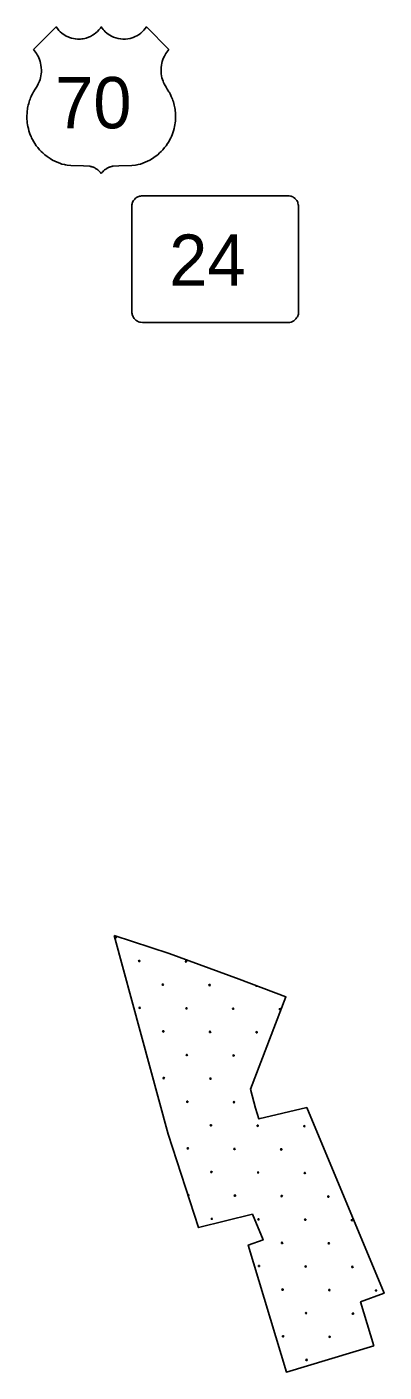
# Model space of a CAD drawing. Extents: x 1612280 to 1883141, y 560852 to 780851.
# Drawn here: x 1797202 to 1800143, y 676727 to 687794 of the extents above; entities that cross this region are included whole.
import ezdxf

# ---------------------------------------------------------------- set-up
doc = ezdxf.new("R2010")
doc.units = 0
for name, color, linetype in [('DESIGN - EROSION CONTROL - Devices', 7, 'Continuous'), ('DESIGN - ROW - Slope Lines', 7, 'Continuous'), ('DESIGN - SCRATCH - User 1', 7, 'Continuous'), ('SURVEY - DRAINAGE - Bridge Deck with Text', 7, 'Continuous')]:
    doc.layers.add(name, color=color, linetype=linetype)

msp = doc.modelspace()

# ---------------------------------------------------------------- linework, layer by layer
at = {"layer": 'DESIGN - EROSION CONTROL - Devices'}
for centre in [(1797933, 680303), (1797933, 680303), (1798127, 680109), (1798127, 680109), (1798512, 680105), (1798512, 680105), (1798321, 679915), (1798321, 679915), (1798706, 679911), (1798706, 679911), (1798131, 679724), (1798131, 679724), (1798516, 679720), (1798516, 679720), (1798900, 679717), (1798900, 679717), (1799285, 679713), (1799285, 679713), (1798325, 679530), (1798325, 679530), (1798710, 679526), (1798710, 679526), (1799094, 679523), (1799094, 679523), (1798519, 679336), (1798519, 679336), (1798904, 679332), (1798904, 679332), (1798329, 679146), (1798329, 679146), (1798714, 679142), (1798714, 679142), (1798523, 678951), (1798523, 678951), (1798908, 678948), (1798908, 678948), (1798717, 678757), (1798717, 678757), (1799102, 678754), (1799102, 678754), (1799486, 678750), (1799486, 678750), (1798527, 678567), (1798527, 678567), (1798911, 678563), (1798911, 678563), (1799296, 678559), (1799296, 678559), (1798721, 678373), (1798721, 678373), (1799106, 678369), (1799106, 678369), (1799490, 678365), (1799490, 678365), (1798915, 678179), (1798915, 678179), (1799300, 678175), (1799300, 678175), (1799684, 678171), (1799684, 678171), (1798725, 677988), (1798725, 677988), (1799109, 677984), (1799109, 677984), (1799494, 677981), (1799494, 677981), (1799878, 677977), (1799878, 677977), (1799303, 677790), (1799303, 677790), (1799688, 677787), (1799688, 677787), (1799113, 677600), (1799113, 677600), (1799498, 677596), (1799498, 677596), (1799882, 677592), (1799882, 677592), (1799307, 677406), (1799307, 677406), (1799692, 677402), (1799692, 677402), (1800076, 677398), (1800076, 677398), (1799501, 677212), (1799501, 677212), (1799886, 677208), (1799886, 677208), (1799311, 677021), (1799311, 677021), (1799695, 677017), (1799695, 677017), (1799505, 676827), (1799505, 676827)]:
    msp.add_circle(centre, 5.28, dxfattribs=at)
for centre, start, end in [((1799091, 679907), 157.0894, 340.6284), ((1798531, 678182), 263.9046, 131.9576)]:
    msp.add_arc(centre, 5.28, start, end, dxfattribs=at)
at = {"layer": 'DESIGN - ROW - Slope Lines'}
msp.add_line((1798066, 686304), (1798066, 685472), dxfattribs=at)
msp.add_line((1798066, 686304), (1798066, 685472), dxfattribs=at)
for points in [[(1799439, 686293), (1799439, 686301), (1799438, 686309), (1799437, 686324), (1799436, 686334), (1799434, 686345), (1799432, 686351), (1799429, 686358), (1799425, 686365), (1799419, 686372), (1799414, 686378), (1799409, 686383), (1799404, 686387), (1799397, 686392), (1799392, 686395), (1799384, 686399), (1799378, 686401), (1799371, 686402), (1799362, 686404), (1799353, 686404), (1799345, 686405), (1799332, 686405), (1799323, 686404), (1798166, 686405), (1798156, 686405), (1798146, 686404), (1798137, 686403), (1798128, 686402), (1798124, 686400), (1798116, 686397), (1798110, 686394), (1798105, 686391), (1798096, 686384), (1798090, 686378), (1798085, 686372), (1798081, 686367), (1798075, 686357), (1798071, 686350), (1798070, 686345), (1798069, 686341), (1798068, 686338), (1798067, 686330), (1798066, 686321), (1798066, 686313), (1798066, 686306), (1798066, 686288)], [(1799439, 686293), (1799439, 686301), (1799438, 686309), (1799437, 686324), (1799436, 686334), (1799434, 686345), (1799432, 686351), (1799429, 686358), (1799425, 686365), (1799419, 686372), (1799414, 686378), (1799409, 686383), (1799404, 686387), (1799397, 686392), (1799392, 686395), (1799384, 686399), (1799378, 686401), (1799371, 686402), (1799362, 686404), (1799353, 686404), (1799345, 686405), (1799332, 686405), (1799323, 686404), (1798166, 686405), (1798156, 686405), (1798146, 686404), (1798137, 686403), (1798128, 686402), (1798124, 686400), (1798116, 686397), (1798110, 686394), (1798105, 686391), (1798096, 686384), (1798090, 686378), (1798085, 686372), (1798081, 686367), (1798075, 686357), (1798071, 686350), (1798070, 686345), (1798069, 686341), (1798068, 686338), (1798067, 686330), (1798066, 686321), (1798066, 686313), (1798066, 686306), (1798066, 686288)], [(1799329, 685363), (1799349, 685363), (1799366, 685363), (1799377, 685366), (1799389, 685370), (1799400, 685377), (1799409, 685384), (1799417, 685392), (1799423, 685400), (1799429, 685409), (1799433, 685417), (1799436, 685424), (1799437, 685432), (1799438, 685440), (1799438, 685450), (1799439, 685473), (1799439, 686293)], [(1799329, 685363), (1799349, 685363), (1799366, 685363), (1799377, 685366), (1799389, 685370), (1799400, 685377), (1799409, 685384), (1799417, 685392), (1799423, 685400), (1799429, 685409), (1799433, 685417), (1799436, 685424), (1799437, 685432), (1799438, 685440), (1799438, 685450), (1799439, 685473), (1799439, 686293)], [(1798066, 685472), (1798066, 685463), (1798066, 685453), (1798067, 685443), (1798068, 685434), (1798070, 685425), (1798073, 685417), (1798076, 685410), (1798080, 685403), (1798086, 685395), (1798091, 685389), (1798099, 685382), (1798106, 685377), (1798114, 685372), (1798122, 685368), (1798131, 685365), (1798138, 685364), (1798153, 685363), (1798172, 685363), (1799329, 685363)], [(1798066, 685472), (1798066, 685463), (1798066, 685453), (1798067, 685443), (1798068, 685434), (1798070, 685425), (1798073, 685417), (1798076, 685410), (1798080, 685403), (1798086, 685395), (1798091, 685389), (1798099, 685382), (1798106, 685377), (1798114, 685372), (1798122, 685368), (1798131, 685365), (1798138, 685364), (1798153, 685363), (1798172, 685363), (1799329, 685363)]]:
    msp.add_lwpolyline(points, dxfattribs=at)
at = {"layer": 'DESIGN - SCRATCH - User 1'}
for points in [[(1797920, 680320), (1798374, 680171), (1798951, 679961), (1799335, 679813), (1799042, 679055)], [(1799060, 678025), (1798615, 677916), (1798366, 678685), (1797920, 680320)], [(1797920, 680320), (1798374, 680171), (1798951, 679961), (1799335, 679813), (1799042, 679055)], [(1799060, 678025), (1798615, 677916), (1798366, 678685), (1797920, 680320)], [(1799042, 679055), (1799085, 678899), (1799113, 678810), (1799506, 678904)], [(1799042, 679055), (1799085, 678899), (1799113, 678810), (1799506, 678904)], [(1799506, 678904), (1800143, 677375), (1799949, 677305), (1800058, 676943)], [(1799506, 678904), (1800143, 677375), (1799949, 677305), (1800058, 676943)], [(1800058, 676943), (1799339, 676727), (1799025, 677772), (1799147, 677815), (1799060, 678025)], [(1800058, 676943), (1799339, 676727), (1799025, 677772), (1799147, 677815), (1799060, 678025)]]:
    msp.add_lwpolyline(points, dxfattribs=at)
at = {"layer": 'SURVEY - DRAINAGE - Bridge Deck with Text'}
for points in [[(1797256, 687608), (1797443, 687794), (1797453, 687781), (1797465, 687766), (1797477, 687754), (1797489, 687744), (1797501, 687734), (1797514, 687726), (1797526, 687719), (1797541, 687712), (1797554, 687707), (1797570, 687702), (1797586, 687698), (1797602, 687695), (1797620, 687694), (1797628, 687694), (1797636, 687694), (1797644, 687694), (1797654, 687695), (1797665, 687697), (1797678, 687699), (1797691, 687702), (1797709, 687709), (1797726, 687716), (1797742, 687725), (1797756, 687734), (1797770, 687745), (1797783, 687756), (1797795, 687769), (1797807, 687783), (1797814, 687794), (1797821, 687784), (1797830, 687773), (1797838, 687764), (1797847, 687755), (1797859, 687744), (1797871, 687735), (1797885, 687726), (1797898, 687719), (1797914, 687711), (1797933, 687704), (1797954, 687699), (1797975, 687695), (1797993, 687694), (1798013, 687694), (1798033, 687696), (1798053, 687700), (1798076, 687707), (1798093, 687714), (1798108, 687722), (1798125, 687732), (1798139, 687743), (1798155, 687757), (1798166, 687768), (1798176, 687780), (1798186, 687794), (1798372, 687608)], [(1797256, 687608), (1797443, 687794), (1797453, 687781), (1797465, 687766), (1797477, 687754), (1797489, 687744), (1797501, 687734), (1797514, 687726), (1797526, 687719), (1797541, 687712), (1797554, 687707), (1797570, 687702), (1797586, 687698), (1797602, 687695), (1797620, 687694), (1797628, 687694), (1797636, 687694), (1797644, 687694), (1797654, 687695), (1797665, 687697), (1797678, 687699), (1797691, 687702), (1797709, 687709), (1797726, 687716), (1797742, 687725), (1797756, 687734), (1797770, 687745), (1797783, 687756), (1797795, 687769), (1797807, 687783), (1797814, 687794), (1797821, 687784), (1797830, 687773), (1797838, 687764), (1797847, 687755), (1797859, 687744), (1797871, 687735), (1797885, 687726), (1797898, 687719), (1797914, 687711), (1797933, 687704), (1797954, 687699), (1797975, 687695), (1797993, 687694), (1798013, 687694), (1798033, 687696), (1798053, 687700), (1798076, 687707), (1798093, 687714), (1798108, 687722), (1798125, 687732), (1798139, 687743), (1798155, 687757), (1798166, 687768), (1798176, 687780), (1798186, 687794), (1798372, 687608)], [(1797256, 687608), (1797265, 687597), (1797273, 687586), (1797281, 687575), (1797287, 687565), (1797294, 687553), (1797300, 687539), (1797306, 687525), (1797311, 687509), (1797315, 687495), (1797318, 687479), (1797320, 687461), (1797322, 687439), (1797321, 687423), (1797320, 687407), (1797318, 687393), (1797314, 687375), (1797310, 687361), (1797305, 687348), (1797300, 687336), (1797296, 687325), (1797288, 687312), (1797281, 687299), (1797270, 687281), (1797257, 687260), (1797254, 687254), (1797248, 687243), (1797241, 687230), (1797237, 687221), (1797232, 687210), (1797228, 687199), (1797224, 687188), (1797220, 687177), (1797217, 687164), (1797213, 687151), (1797211, 687140), (1797208, 687127), (1797206, 687116), (1797205, 687103), (1797203, 687091), (1797203, 687080), (1797202, 687069), (1797202, 687058), (1797202, 687045), (1797202, 687034), (1797204, 687019), (1797205, 687004), (1797207, 686989), (1797210, 686974), (1797214, 686958), (1797219, 686939), (1797224, 686924), (1797230, 686906), (1797236, 686893), (1797241, 686881), (1797249, 686867), (1797258, 686849), (1797267, 686834), (1797279, 686817), (1797292, 686801), (1797306, 686784), (1797320, 686769), (1797333, 686757), (1797350, 686742), (1797369, 686727), (1797394, 686711), (1797414, 686699), (1797433, 686689), (1797451, 686681), (1797472, 686673), (1797491, 686666), (1797511, 686661), (1797521, 686659), (1797533, 686657), (1797563, 686654), (1797669, 686651), (1797717, 686649), (1797721, 686648), (1797726, 686647), (1797731, 686646), (1797736, 686644), (1797741, 686643), (1797746, 686641), (1797751, 686639), (1797755, 686637), (1797760, 686634), (1797764, 686632), (1797768, 686630), (1797777, 686625), (1797786, 686618), (1797795, 686611), (1797802, 686603), (1797809, 686596), (1797814, 686587)], [(1797256, 687608), (1797265, 687597), (1797273, 687586), (1797281, 687575), (1797287, 687565), (1797294, 687553), (1797300, 687539), (1797306, 687525), (1797311, 687509), (1797315, 687495), (1797318, 687479), (1797320, 687461), (1797322, 687439), (1797321, 687423), (1797320, 687407), (1797318, 687393), (1797314, 687375), (1797310, 687361), (1797305, 687348), (1797300, 687336), (1797296, 687325), (1797288, 687312), (1797281, 687299), (1797270, 687281), (1797257, 687260), (1797254, 687254), (1797248, 687243), (1797241, 687230), (1797237, 687221), (1797232, 687210), (1797228, 687199), (1797224, 687188), (1797220, 687177), (1797217, 687164), (1797213, 687151), (1797211, 687140), (1797208, 687127), (1797206, 687116), (1797205, 687103), (1797203, 687091), (1797203, 687080), (1797202, 687069), (1797202, 687058), (1797202, 687045), (1797202, 687034), (1797204, 687019), (1797205, 687004), (1797207, 686989), (1797210, 686974), (1797214, 686958), (1797219, 686939), (1797224, 686924), (1797230, 686906), (1797236, 686893), (1797241, 686881), (1797249, 686867), (1797258, 686849), (1797267, 686834), (1797279, 686817), (1797292, 686801), (1797306, 686784), (1797320, 686769), (1797333, 686757), (1797350, 686742), (1797369, 686727), (1797394, 686711), (1797414, 686699), (1797433, 686689), (1797451, 686681), (1797472, 686673), (1797491, 686666), (1797511, 686661), (1797521, 686659), (1797533, 686657), (1797563, 686654), (1797669, 686651), (1797717, 686649), (1797721, 686648), (1797726, 686647), (1797731, 686646), (1797736, 686644), (1797741, 686643), (1797746, 686641), (1797751, 686639), (1797755, 686637), (1797760, 686634), (1797764, 686632), (1797768, 686630), (1797777, 686625), (1797786, 686618), (1797795, 686611), (1797802, 686603), (1797809, 686596), (1797814, 686587)], [(1798372, 687608), (1798363, 687597), (1798355, 687587), (1798347, 687575), (1798341, 687565), (1798334, 687553), (1798328, 687539), (1798322, 687525), (1798317, 687509), (1798313, 687495), (1798310, 687479), (1798308, 687461), (1798307, 687439), (1798307, 687423), (1798308, 687407), (1798311, 687393), (1798314, 687375), (1798318, 687361), (1798323, 687348), (1798328, 687336), (1798333, 687325), (1798340, 687312), (1798348, 687299), (1798358, 687281), (1798371, 687260), (1798375, 687254), (1798381, 687243), (1798387, 687230), (1798391, 687221), (1798396, 687210), (1798400, 687199), (1798404, 687188), (1798408, 687177), (1798412, 687164), (1798415, 687151), (1798418, 687140), (1798420, 687128), (1798422, 687116), (1798424, 687103), (1798425, 687091), (1798426, 687080), (1798426, 687069), (1798426, 687058), (1798426, 687045), (1798426, 687034), (1798425, 687019), (1798423, 687004), (1798421, 686989), (1798418, 686974), (1798414, 686958), (1798409, 686939), (1798404, 686924), (1798398, 686906), (1798392, 686893), (1798387, 686881), (1798380, 686867), (1798370, 686849), (1798361, 686834), (1798349, 686817), (1798336, 686801), (1798322, 686784), (1798308, 686769), (1798295, 686757), (1798279, 686742), (1798259, 686727), (1798235, 686711), (1798214, 686699), (1798195, 686689), (1798177, 686681), (1798156, 686673), (1798137, 686666), (1798117, 686661), (1798108, 686659), (1798095, 686657), (1798065, 686654), (1797959, 686651), (1797912, 686649), (1797907, 686648), (1797902, 686647), (1797897, 686646), (1797892, 686644), (1797887, 686643), (1797883, 686641), (1797877, 686639), (1797873, 686637), (1797868, 686634), (1797864, 686632), (1797860, 686630), (1797851, 686625), (1797842, 686618), (1797834, 686611), (1797826, 686603), (1797820, 686596), (1797814, 686587)], [(1798372, 687608), (1798363, 687597), (1798355, 687587), (1798347, 687575), (1798341, 687565), (1798334, 687553), (1798328, 687539), (1798322, 687525), (1798317, 687509), (1798313, 687495), (1798310, 687479), (1798308, 687461), (1798307, 687439), (1798307, 687423), (1798308, 687407), (1798311, 687393), (1798314, 687375), (1798318, 687361), (1798323, 687348), (1798328, 687336), (1798333, 687325), (1798340, 687312), (1798348, 687299), (1798358, 687281), (1798371, 687260), (1798375, 687254), (1798381, 687243), (1798387, 687230), (1798391, 687221), (1798396, 687210), (1798400, 687199), (1798404, 687188), (1798408, 687177), (1798412, 687164), (1798415, 687151), (1798418, 687140), (1798420, 687128), (1798422, 687116), (1798424, 687103), (1798425, 687091), (1798426, 687080), (1798426, 687069), (1798426, 687058), (1798426, 687045), (1798426, 687034), (1798425, 687019), (1798423, 687004), (1798421, 686989), (1798418, 686974), (1798414, 686958), (1798409, 686939), (1798404, 686924), (1798398, 686906), (1798392, 686893), (1798387, 686881), (1798380, 686867), (1798370, 686849), (1798361, 686834), (1798349, 686817), (1798336, 686801), (1798322, 686784), (1798308, 686769), (1798295, 686757), (1798279, 686742), (1798259, 686727), (1798235, 686711), (1798214, 686699), (1798195, 686689), (1798177, 686681), (1798156, 686673), (1798137, 686666), (1798117, 686661), (1798108, 686659), (1798095, 686657), (1798065, 686654), (1797959, 686651), (1797912, 686649), (1797907, 686648), (1797902, 686647), (1797897, 686646), (1797892, 686644), (1797887, 686643), (1797883, 686641), (1797877, 686639), (1797873, 686637), (1797868, 686634), (1797864, 686632), (1797860, 686630), (1797851, 686625), (1797842, 686618), (1797834, 686611), (1797826, 686603), (1797820, 686596), (1797814, 686587)]]:
    msp.add_lwpolyline(points, dxfattribs=at)

# ---------------------------------------------------------------- texts
at = {"layer": 'DESIGN - ROW - Slope Lines'}
msp.add_text('24', height=422.4, rotation=0.0011, dxfattribs=at).set_placement((1798374, 685664))
msp.add_text('24', height=422.4, rotation=0.0011, dxfattribs=at).set_placement((1798374, 685664))
at = {"layer": 'SURVEY - DRAINAGE - Bridge Deck with Text'}
msp.add_text('70', height=422.4, rotation=0.0013, dxfattribs=at).set_placement((1797435, 686960))
msp.add_text('70', height=422.4, rotation=0.0013, dxfattribs=at).set_placement((1797435, 686960))

doc.saveas('drawing.dxf')
